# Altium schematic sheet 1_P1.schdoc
size 307 x 218 mm; Symbol: Drawing-Symbol_A4; Device: Drawing-Symbol_A4; @Project Name: temp; @Page Count: 1; @Update Date: 2025-07-16; @Create Date: 2025-07-16; @Schematic Name: Schematic1; @Page No: 1; @Page Name: P1; Version: V1.0; Page Size: A4; @Create Time: 03:18:36; @Update Time: 08:48:36; Width: 1170; Height: 825; Region Start: 1; X Region Count: 6; Y Region Count: 4; Blade Width: 10; Title Block Position: 3; @Board Name: Board1
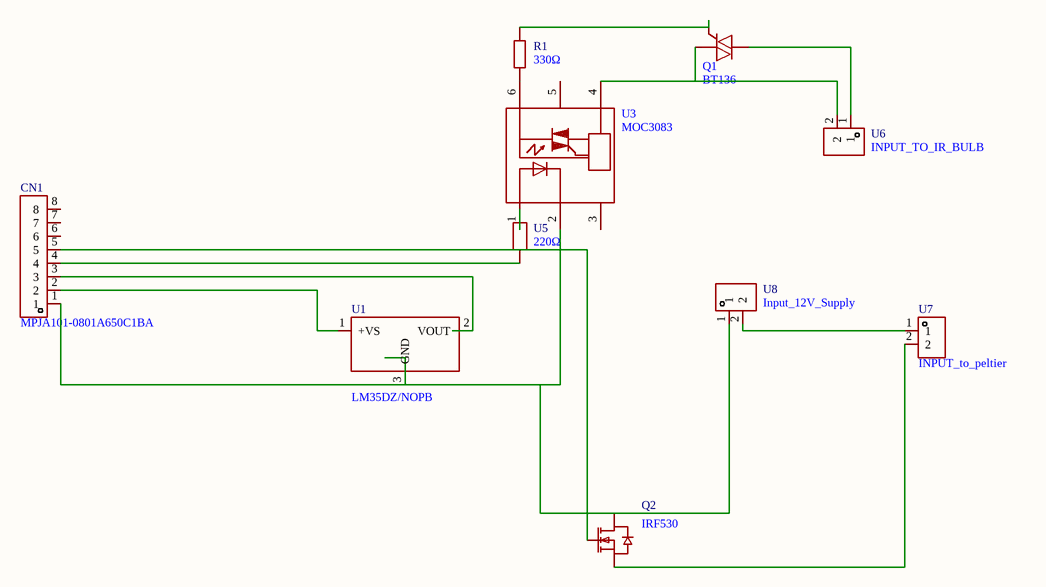
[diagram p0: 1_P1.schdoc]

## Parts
CN1  MPJA101-0801A650C1BA  [HDR-TH_8P-P3.96-V-M_C9900009548]
Q1  BT136  [TO-220-3_L10.0-W4.5-P2.54-T]
Q2  IRF530  [TO-220AB-3_L10.4-W4.6-P2.54-L]
R1  330Ω  [R0603]
U1  LM35DZ/NOPB  [TO-92-3_L4.9-W3.7-P1.27-L]
U3  MOC3083  [DIP-6_L7.1-W6.5-P2.54-LS7.6-BL]
U5  220Ω  [TO-220-2_L10.2-W4.6-P2.54-L]
U6  INPUT_TO_IR_BULB  [CONN-TH_2P-P3.81_DB2EVC-3.81-2P-WT]
U7  INPUT_to_peltier  [CONN-TH_2P-P3.81_DB2EVC-3.81-2P-WT]
U8  Input_12V_Supply  [CONN-TH_2P-P3.81_DB2EVC-3.81-2P-WT]

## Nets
NetCN1_1: CN1.1 Q2.2(D) U1.3(GND) U3.2(CAT) U8.1
NetCN1_2: CN1.2 U1.1(+VS)
NetCN1_3: CN1.3 U1.2(VOUT)
NetCN1_4: CN1.4 U5.1
NetCN1_5: CN1.5 Q2.1(G)
NetQ1_1: Q1.1(M1) U3.4(MT) U6.2
NetQ1_2: Q1.2(M2) U6.1
NetQ1_3: Q1.3(G) R1.2
NetQ2_3: Q2.3(S) U7.2
NetR1_1: R1.1 U3.6(MT)
NetU3_1: U3.1(AN) U5.2
NetU7_1: U7.1 U8.2

Not connected (* = marked no-connect by the designer): CN1 6 7 8; U3 3(NC) 5(NC*)

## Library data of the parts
CN1 = MPJA101-0801A650C1BA: Add into BOM: yes
Q1 = BT136: Manufacturer: CJ(江苏长电/长晶); Add into BOM: yes; SCR Type: 1个双向可控硅; Gate Trigger   Voltage (Vgt): 1.45V; Holding Current (Ih): 20mA; Peak Repetitive Off?State Voltage (Vdrm): 600V; Gate Trigger Current(Igt): 10mA; Peak Forward On?State Voltage (Vtm): 1.7V; Peak non-repetitive surge current (Itsm@f): 25A@25ms; Average Gate Power Dissipation (PG(AV)): 500mW; RMS On-State Current(It (rms)): 6A
Q2 = IRF530: Manufacturer: TI(德州仪器); Add into BOM: yes; Type: 1 N-channel; Drain to Source Voltage: 100V; Current - Continuous Drain(Id): 14A; RDS(on): 180mΩ@10V,8A; Pd - Power Dissipation: 75W; Gate Threshold Voltage (Vgs(th)@Id): 4V; Input Capacitance(Ciss@Vds): 800pF@25V
R1 = 0603WAF3300T5E: Manufacturer: UNI-ROYAL(厚声); Add into BOM: yes; Tolerance: ±1%; Temperature Coefficient: ±100ppm/℃
U1 = LM35DZ/NOPB_C12165: Manufacturer: TI(德州仪器); Symbol: LM35DZ; Add into BOM: yes; Resolution: ±1.5℃; Supply Voltage: 4V~30V
U3 = MOC3083: Manufacturer: LITEON(光宝); Add into BOM: yes; Output Type: Two-way thyristor; Voltage - Forward(Vf): 1.4V; Output Current(It(rms)): 1A; Isolation Voltage(Vrms): 5kV; Forward Current: 20mA; Load Voltage: 800V; Static dv/dt: 1500V/us; Number of Outputs: 1
U5 = TCH35P220RJE: Manufacturer: Ohmite; Add into BOM: yes; Tolerance: ±5%; Power(Watts): 35W; Temperature Coefficient: ±50ppm/℃
U6-U8 = TERM BLOCK HDR 2POS VERT 3.81M: Add into BOM: yes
